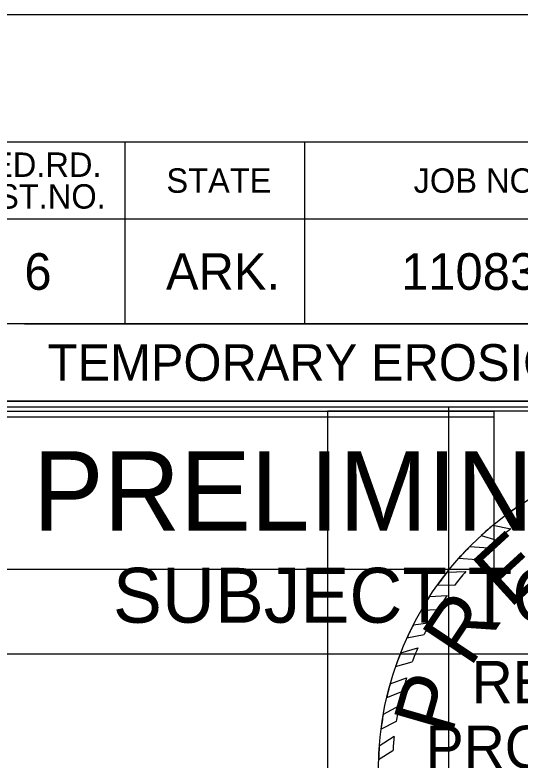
# Model space of a CAD drawing. Extents: x -0.29 to 1.42, y 0 to 0.92.
# Drawn here: x 1.2237 to 1.3066, y 0.7945 to 0.9167 of the extents above; entities that cross this region are included whole.
import ezdxf

# ---------------------------------------------------------------- set-up
doc = ezdxf.new("R2010")
doc.units = 0
for name, color, linetype in [('DSN_DRFT_Guideline-No-Plot', 7, 'Continuous'), ('SHET_Annotations', 7, 'Continuous'), ('SHET_Border-Lines', 7, 'Continuous'), ('SHET_Border-Text', 7, 'Continuous'), ('SHET_Stamp-Prelim', 7, 'Continuous'), ('SHET_Stamp-Seal', 7, 'Continuous'), ('STAMP_PE DIG SIG', 7, 'Continuous'), ('STAMP_PE_BACKGROUND', 7, 'Continuous'), ('STAMP_PE_SEAL-INFO', 7, 'Continuous'), ('STAMP_PRELIMINARY', 7, 'Continuous')]:
    doc.layers.add(name, color=color, linetype=linetype)

msp = doc.modelspace()

# ---------------------------------------------------------------- linework, layer by layer
at = {"layer": 'DSN_DRFT_Guideline-No-Plot'}
msp.add_lwpolyline([(0, 0), (1.416666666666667, 0), (1.416666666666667, 0.9166666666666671), (0, 0.9166666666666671)], close=True, dxfattribs=at)
at = {"layer": 'SHET_Border-Lines'}
for p, q in [((1.2417314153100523, 0.8958333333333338), (1.2417314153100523, 0.8660136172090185)), ((1.271225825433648, 0.8958333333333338), (1.271225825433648, 0.8660136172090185)), ((1.3958333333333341, 0.8832007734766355), (1.2126619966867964, 0.8832007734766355)), ((1.3958333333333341, 0.8660136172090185), (1.2126619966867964, 0.8660136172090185)), ((1.2252417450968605, 0.8660136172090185), (1.3958333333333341, 0.8660136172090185)), ((1.3958333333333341, 0.8533810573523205), (1.1296186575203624, 0.8533810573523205))]:
    msp.add_line(p, q, dxfattribs=at)
for points in [[(0.02083333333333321, 0.02083333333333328), (1.3958333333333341, 0.02083333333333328), (1.3958333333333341, 0.8958333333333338), (0.02083333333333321, 0.8958333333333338)], [(1.1296186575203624, 0.8533810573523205), (1.3958333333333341, 0.8533810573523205), (1.3958333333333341, 0.8958333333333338), (1.1296186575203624, 0.8958333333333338)]]:
    msp.add_lwpolyline(points, close=True, dxfattribs=at)
at = {"layer": 'SHET_Stamp-Prelim'}
msp.add_lwpolyline([(1.2136619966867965, 0.8119287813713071), (1.3948333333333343, 0.8119287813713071), (1.3948333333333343, 0.8523810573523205), (1.2136619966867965, 0.8523810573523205)], close=True, dxfattribs=at)
at = {"layer": 'SHET_Stamp-Seal'}
msp.add_lwpolyline([(1.2948333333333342, 0.7523810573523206), (1.3948333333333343, 0.7523810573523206), (1.3948333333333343, 0.8523810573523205), (1.2948333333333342, 0.8523810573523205)], close=True, dxfattribs=at)
at = {"layer": 'STAMP_PE DIG SIG'}
msp.add_lwpolyline([(1.20224533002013, 0.8507768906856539), (1.3022453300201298, 0.8507768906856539), (1.3022453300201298, 0.8257768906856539), (1.20224533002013, 0.8257768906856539)], close=True, dxfattribs=at)
msp.add_lwpolyline([(1.20224533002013, 0.8507768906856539), (1.3022453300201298, 0.8507768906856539), (1.3022453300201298, 0.8257768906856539), (1.20224533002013, 0.8257768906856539)], close=True, dxfattribs=at)
at = {"layer": 'STAMP_PE_BACKGROUND'}
for points in [[(1.20224533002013, 0.8517143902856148), (1.3022453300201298, 0.8517143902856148), (1.3022453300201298, 0.8257768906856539), (1.20224533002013, 0.8257768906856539)], [(1.20224533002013, 0.8517143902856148), (1.3022453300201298, 0.8517143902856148), (1.3022453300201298, 0.8257768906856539), (1.20224533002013, 0.8257768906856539)], [(1.3941666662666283, 0.8517143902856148), (1.2749999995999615, 0.8517143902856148), (1.2749999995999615, 0.7325477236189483), (1.3941666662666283, 0.7325477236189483)], [(1.3941666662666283, 0.8517143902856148), (1.2749999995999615, 0.8517143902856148), (1.2749999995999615, 0.7325477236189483), (1.3941666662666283, 0.7325477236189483)]]:
    msp.add_lwpolyline(points, close=True, dxfattribs=at)
at = {"layer": 'STAMP_PE_SEAL-INFO'}
for p, q in [((1.304230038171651, 0.834845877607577), (1.3067758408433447, 0.8337010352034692)), ((1.304230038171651, 0.834845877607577), (1.3067758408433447, 0.8337010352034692)), ((1.3021247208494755, 0.833018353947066), (1.3050815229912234, 0.8324555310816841)), ((1.3021247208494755, 0.833018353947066), (1.3050815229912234, 0.8324555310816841)), ((1.300204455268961, 0.8313411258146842), (1.3027675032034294, 0.8305649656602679)), ((1.300204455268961, 0.8313411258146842), (1.3027675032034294, 0.8305649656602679)), ((1.2983306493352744, 0.8295335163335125), (1.3013705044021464, 0.8293048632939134)), ((1.2983306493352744, 0.8295335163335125), (1.3013705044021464, 0.8293048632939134)), ((1.2965273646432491, 0.8276096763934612), (1.2994411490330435, 0.8273959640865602)), ((1.2965273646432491, 0.8276096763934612), (1.2994411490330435, 0.8273959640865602)), ((1.2945961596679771, 0.8253118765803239), (1.29766304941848, 0.8254364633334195)), ((1.2945961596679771, 0.8253118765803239), (1.29766304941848, 0.8254364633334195)), ((1.293041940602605, 0.8232473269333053), (1.295863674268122, 0.8232188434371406)), ((1.293041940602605, 0.8232473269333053), (1.295863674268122, 0.8232188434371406)), ((1.2917323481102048, 0.8213255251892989), (1.2946152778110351, 0.8215129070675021)), ((1.2917323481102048, 0.8213255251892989), (1.2946152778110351, 0.8215129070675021)), ((1.2903571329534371, 0.8190854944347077), (1.2930895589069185, 0.8191977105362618)), ((1.2903571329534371, 0.8190854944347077), (1.2930895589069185, 0.8191977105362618)), ((1.2890663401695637, 0.8167198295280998), (1.2918496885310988, 0.8170826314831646)), ((1.2890663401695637, 0.8167198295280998), (1.2918496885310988, 0.8170826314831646)), ((1.2880157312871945, 0.8145473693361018), (1.290823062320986, 0.8151270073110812)), ((1.2880157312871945, 0.8145473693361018), (1.290823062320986, 0.8151270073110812)), ((1.2869882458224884, 0.8121310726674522), (1.2898051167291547, 0.8129483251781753)), ((1.2869882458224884, 0.8121310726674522), (1.2898051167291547, 0.8129483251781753)), ((1.286150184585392, 0.8098607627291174), (1.2888550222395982, 0.8106218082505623)), ((1.286150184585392, 0.8098607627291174), (1.2888550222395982, 0.8106218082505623)), ((1.2852747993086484, 0.807052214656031), (1.2879416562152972, 0.80799417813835)), ((1.2852747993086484, 0.807052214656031), (1.2879416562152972, 0.80799417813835)), ((1.2846899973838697, 0.8047744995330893), (1.2873158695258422, 0.8058517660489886)), ((1.2846899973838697, 0.8047744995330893), (1.2873158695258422, 0.8058517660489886)), ((1.2867248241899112, 0.8033987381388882), (1.284124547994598, 0.8020082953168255)), ((1.2867248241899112, 0.8033987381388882), (1.284124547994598, 0.8020082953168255)), ((1.2862455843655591, 0.8008368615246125), (1.2837569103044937, 0.799593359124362)), ((1.2862455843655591, 0.8008368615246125), (1.2837569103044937, 0.799593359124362)), ((1.2859172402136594, 0.7984029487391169), (1.2834771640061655, 0.7968324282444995)), ((1.2859172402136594, 0.7984029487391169), (1.2834771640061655, 0.7968324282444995)), ((1.2857136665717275, 0.796027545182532), (1.2833588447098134, 0.7945943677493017)), ((1.2857136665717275, 0.796027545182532), (1.2833588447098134, 0.7945943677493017))]:
    msp.add_line(p, q, dxfattribs=at)
for radius, start, end in [(0.05208333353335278, 123.61993215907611, 126.59062794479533), (0.05208333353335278, 123.61993215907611, 126.59062794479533), (0.05208333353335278, 129.73259019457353, 132.53764328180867), (0.05208333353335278, 129.73259019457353, 132.53764328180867), (0.04979730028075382, 127.5296898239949, 130.96828939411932), (0.04979730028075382, 127.5296898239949, 130.96828939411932), (0.05208333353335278, 135.40207922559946, 138.30313604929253), (0.05208333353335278, 135.40207922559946, 138.30313604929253), (0.04979730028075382, 133.13305755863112, 136.25622701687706), (0.04979730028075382, 133.13305755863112, 136.25622701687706), (0.05208333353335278, 141.60555977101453, 144.4486483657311), (0.05208333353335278, 141.60555977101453, 144.4486483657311), (0.04979730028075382, 139.30101253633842, 142.58728849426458), (0.04979730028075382, 139.30101253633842, 142.58728849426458), (0.05208333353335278, 147.00719016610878, 149.8990425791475), (0.05208333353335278, 147.00719016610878, 149.8990425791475), (0.04979730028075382, 145.0197202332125, 148.2103639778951), (0.04979730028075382, 145.0197202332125, 148.2103639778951), (0.05208333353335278, 152.8639823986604, 155.51889127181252), (0.05208333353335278, 152.8639823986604, 155.51889127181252), (0.04979730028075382, 151.03152721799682, 153.57304034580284), (0.04979730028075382, 151.03152721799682, 153.57304034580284), (0.04979730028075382, 156.3401777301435, 159.23193612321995), (0.04979730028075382, 156.3401777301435, 159.23193612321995), (0.05208333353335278, 158.40765685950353, 161.07014519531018), (0.05208333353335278, 158.40765685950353, 161.07014519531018), (0.04979730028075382, 162.43309106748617, 165.00132712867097), (0.04979730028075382, 162.43309106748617, 165.00132712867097), (0.05208333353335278, 164.306798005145, 166.89395340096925), (0.05208333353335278, 164.306798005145, 166.89395340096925), (0.04979730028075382, 167.9048137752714, 170.90393120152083), (0.04979730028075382, 167.9048137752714, 170.90393120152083), (0.05208333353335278, 170.00030285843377, 172.68777762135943), (0.05208333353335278, 170.00030285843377, 172.68777762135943), (0.04979730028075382, 173.72999663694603, 176.47336897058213), (0.04979730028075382, 173.72999663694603, 176.47336897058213), (0.05208333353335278, 175.7409317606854, 178.20660347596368), (0.05208333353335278, 175.7409317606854, 178.20660347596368)]:
    msp.add_arc((1.3354166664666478, 0.7929643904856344), radius, start, end, dxfattribs=at)
at = {"layer": 'STAMP_PRELIMINARY'}
msp.add_circle((1.3354166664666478, 0.7929643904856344), 0.05208333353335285, dxfattribs=at)
msp.add_circle((1.3354166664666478, 0.7929643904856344), 0.05208333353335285, dxfattribs=at)

# ---------------------------------------------------------------- texts
at = {"layer": 'SHET_Annotations'}
for s, p in [('6', (1.225240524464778, 0.8716071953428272)), ('ARK.', (1.2484719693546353, 0.8716071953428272)), ('110831', (1.2870604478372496, 0.8716071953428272)), ('TEMPORARY EROSION CONTROL DETAILS', (1.2290559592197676, 0.8566973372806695))]:
    msp.add_text(s, height=0.006000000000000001, dxfattribs=at).set_placement(p)
at = {"layer": 'SHET_Border-Text'}
for s, p in [('FED.RD.', (1.2165058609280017, 0.8901170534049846)), ('STATE', (1.2485426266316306, 0.8875170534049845)), ('JOB NO.', (1.2891034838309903, 0.8875170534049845)), ('DIST.NO.', (1.2154146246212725, 0.8849170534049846))]:
    msp.add_text(s, height=0.004, dxfattribs=at).set_placement(p)
at = {"layer": 'SHET_Stamp-Prelim'}
for s, height, p in [('PRELIMINARY', 0.013, (1.2266349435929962, 0.8321549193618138)), ('SUBJECT TO REVISION', 0.009, (1.239775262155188, 0.8170418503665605))]:
    msp.add_text(s, height=height, dxfattribs=at).set_placement(p)
at = {"layer": 'STAMP_PE_SEAL-INFO'}
for s, p in [('REGISTERED', (1.298637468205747, 0.8038080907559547)), ('REGISTERED', (1.298637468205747, 0.8038080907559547)), ('PROFESSIONAL', (1.2911053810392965, 0.7931852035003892)), ('PROFESSIONAL', (1.2911053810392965, 0.7931852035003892))]:
    msp.add_text(s, height=0.006983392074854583, dxfattribs=at).set_placement(p)
at = {"layer": 'STAMP_PRELIMINARY'}
for s, rotation, p in [('E', 42.3578427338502, (1.304835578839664, 0.8192021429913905)), ('E', 42.3578427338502, (1.304835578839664, 0.8192021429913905)), ('R', 56.22922398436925, (1.2983799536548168, 0.8095225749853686)), ('R', 56.22922398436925, (1.2983799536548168, 0.8095225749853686)), ('P', 73.91301312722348, (1.2953111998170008, 0.7982181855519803)), ('P', 73.91301312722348, (1.2953111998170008, 0.7982181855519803))]:
    msp.add_text(s, height=0.010056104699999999, rotation=rotation, dxfattribs=at).set_placement(p)

doc.saveas('drawing.dxf')
